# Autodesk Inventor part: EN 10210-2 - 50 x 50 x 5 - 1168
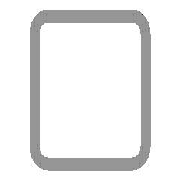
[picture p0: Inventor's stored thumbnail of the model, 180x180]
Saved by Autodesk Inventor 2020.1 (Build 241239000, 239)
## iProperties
_CCFamilyMember: 16
_CCFamilyDisplayName: DIN EN 10210-2 (USAS B17.1 quadratisch) - Rohrleitung — In Klammern angegebene Größen wurden aufgehoben
_FrameMemberDoc: Frame Member File
_Version: 15.0.0
_GetPNFromCC: 1
IsCustomPart: 1
Created: 2019-01
Part Number: EN 10210-2 - 50 x 50 x 5 - 1168
Material: Stahl, weich
Description: Rohrleitung
Document SubType Name: Modeling
Standard: DIN
Designer: lutzd
Standard Revision: 2006-07
Standards Organization: DIN
Language: de-DE
Size Designation: 50 x 50 x 5
Categories: <MemberInstance><Categories><Category DisplayName="Profile" InternalName="089c4875-fa83-4c05-b084-43b9cc11f5ed" Mnemonic="GRDR"><CategoryParameter DisplayName="
Stock Number: 50 x 50 x 5
Mass: 7948.88 g
Surface Area: 3970.32 cm^2
Volume: 1012.6 cm^3
Density: 7.85 g/cm^3
Appearance: Halbpoliert
G_L: 1168,000 mm
G_W: 50,000 mm
G_H: 50,000 mm
Dimensions: 50x50x1168 mm
Mass: 7,949 kg
DocNumber: ADSK-014176
Folder: .
Title: Profil-Bauteil
Author: lutzd
Revision Number: -
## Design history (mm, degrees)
node "Startebene"
node "Endebene"
sketch "Skizze"
  geometry: L1 (-25, -17.5)-(-25, 17.5); L2 (-17.5, 25)-(17.5, 25); L3 (25, 17.5)-(25, -17.5); L4 (17.5, -25)-(-17.5, -25); L5 (-15, 20)-(15, 20); L6 (20, 15)-(20, -15); L7 (15, -20)-(-15, -20); L8 (-20, -15)-(-20, 15); L9 (0, 37.175)-(0, -37.175) reference; L10 (-37.175, 0)-(37.175, 0) reference; A1 r 7.5 centre (-17.5, -17.5) between (-25, -17.5) and (-17.5, -25); A2 r 7.5 centre (-17.5, 17.5) between (-17.5, 25) and (-25, 17.5); A3 r 7.5 centre (17.5, 17.5) between (25, 17.5) and (17.5, 25); A4 r 7.5 centre (17.5, -17.5) between (17.5, -25) and (25, -17.5); A5 r 5 centre (-15, -15) between (-20, -15) and (-15, -20); A6 r 5 centre (-15, 15) between (-15, 20) and (-20, 15); A7 r 5 centre (15, 15) between (20, 15) and (15, 20); A8 r 5 centre (15, -15) between (15, -20) and (20, -15)
  constraints: 16 end point, 16 point on circle, 16 tangent, 8 centre point, 6 equal radius, 4 parallel, 2 perpendicular, 2 other
  dimensions: "d7" = 7.5 radius of A1 (= G_IR); "d10" = 50 distance between parallel lines of L2 L4 (= G_H); "d11" = 50 distance between parallel lines of L1 L3 (= G_W); "d12" = 5 distance between parallel lines of L3 L6 (= G_T); "d15" = 25 distance between parallel lines of L2 L10 (= 0.5 x d10); "d16" = 25 distance between parallel lines of L9 L3 (= 0.5 x d11); "d19" = 5 radius of A5 (= G_T); "d20" = 5 distance between parallel lines of L4 L7 (= G_T)
extrude "Körper" new body sketch "Skizze" stored distance "d3" = 1168 (= G_L); taper "d4" = 0 deg
node "Driven Length"
  sketch "Sketch3"
    geometry: L1 (0, 0)-(10, 0) reference
    constraints: 2 end point, 1 horizontal
  workplane "Work Plane3"
  sketch "Sketch4"
    geometry: L1 (-2, 0)-(12, 0) reference; L2 (-2, 1168)-(12, 1168) reference
    dimensions: "d18" = 1168 distance between parallel lines of L1 L2 (derived)
workplane "Arbeitsebene4"
feature "Trennen1"
sketch "Skizze5"
  geometry: L1 (0, 35)-(0, 0) reference; L2 (1168, 35)-(1168, 0) reference; L3 (1168, 17.5)-(0, 17.5); L4 (1116.5, 34)-(1149.5, 34); L5 (1149.5, 34)-(1149.5, 1); L6 (1149.5, 1)-(1116.5, 1); L7 (1116.5, 1)-(1116.5, 34); 7 further points
  constraints: 10 end point, 3 midpoint, 3 point on line, 2 coincident, 2 parallel, 1 horizontal, 1 horizontal alignment, 1 perpendicular, 1 vertical alignment
  dimensions: "d23" = 25 distance of point (632.5, 17.5) point (607.5, 17.5); "d27" = 35 distance from line of L2 point (1133, 17.5); "d42" = 33 distance of L6.end L4.start; "d43" = 33 distance of L4.start L4.end (= d42); "d82" = 607.5 distance from line of L1 point (607.5, 17.5)
hole "Bohrung2" sketch "Skizze5" diameter "d35" = 22; stored, may be unused: countersink angle "d39" = 90 deg, drill point angle "d41" = 118 deg; dims "d36" = 16, "d37" = 4, "d38" = 2, "d40" = 22.2
sketch "Skizze6"
  geometry: L1 (-35, 0)-(0, 0) reference; L2 (-17.5, 1168)-(-17.5, 0); 4 further points
  constraints: 4 point on line, 2 end point, 1 midpoint
  dimensions: "d51" = 25 distance of point (-17.5, 100) point (-17.5, 75); "d52" = 25 distance of point (-17.5, 607) point (-17.5, 582) (= d51); "d53" = 482 distance of point (-17.5, 582) point (-17.5, 100); "d54" = 75 distance from line of point (-17.5, 75) L1
hole "Bohrung4" sketch "Skizze6" at (-17.5, 75), (-17.5, 100), (-17.5, 582), (-17.5, 607) diameter "d55" = 6.647; stored, may be unused: countersink angle "d59" = 90 deg, drill point angle "d61" = 118 deg; dims "d56" = 16, "d57" = 18, "d58" = 4.8, "d60" = 22.2
sketch "Skizze7"
  geometry: L1 (0, 0)-(0, 35) reference; L2 (1168, 0)-(1168, 35) reference; 11 further points
  constraints: 1 coincident, 11 other
  dimensions: "d62" = 41 distance of point (422, 17.5) point (381, 17.5); "d63" = 41 distance of point (254, 17.5) point (295, 17.5) (= d62); "d64" = 254 distance from line of L1 point (254, 17.5); "d76" = 140 distance from line of L1 point (140, 17.5); "d77" = 25 distance of point (165, 17.5) point (140, 17.5); "d78" = 127 distance of point (381, 17.5) point (254, 17.5); "d79" = 25 distance of point (1154.5, 17.5) point (1129.5, 17.5); "d80" = 12.5 distance of point (1129.5, 17.5) point (1142, 17.5) (= 0.5 x d79); "d81" = 26 distance from line of L2 point (1142, 17.5)
hole "Bohrung5" sketch "Skizze7" at (254, 17.5), (295, 17.5), (381, 17.5), (422, 17.5), (165, 17.5), (140, 17.5), (1154.5, 17.5), (1129.5, 17.5) diameter "d66" = 6.647; stored, may be unused: countersink angle "d70" = 90 deg, drill point angle "d72" = 118 deg; dims "d67" = 16, "d68" = 4, "d69" = 2, "d71" = 5
body "Solid1"
other parameters: "G_W" = 50 [user parameter; used in 1 equation term], "G_H" = 50 [user parameter; used in 1 equation term], "G_T" = 5 [user parameter; used in 3 equation terms], "G_IR" = 7.5 [user parameter; used in 1 equation term], "G_L" = 1168 (= d18) [user parameter; used in 1 equation term], "G_OFFSET_START" = 0 [user parameter; used in 1 equation term], "G_OFFSET_END" = 25 [user parameter; used in 1 equation term], "d13" = 0 (computed from G_OFFSET_START), "d14" = 1168 (= G_OFFSET_END + B_L), "B_L" = 1143 [user parameter; used in 1 equation term], "d17" = 90 deg
